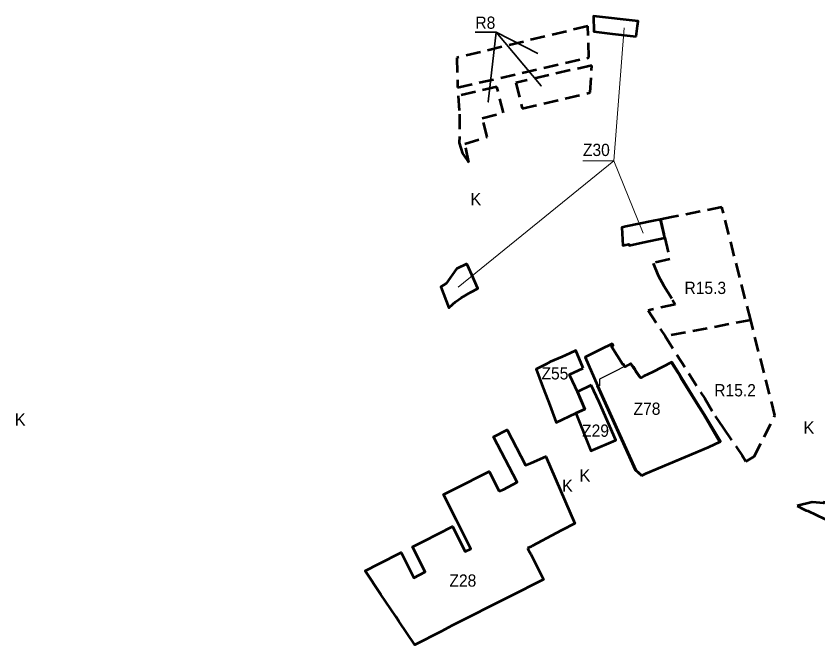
# Model space of a CAD drawing. Extents: x -650246 to -642674, y -1074280 to -1066767.
# Drawn here: x -649378 to -647810, y -1067997 to -1066767 of the extents above; entities that cross this region are included whole.
import ezdxf

# ---------------------------------------------------------------- set-up
doc = ezdxf.new("R2010")
doc.units = 0
doc.header["$LTSCALE"] = 9.6
doc.linetypes.add('MEDIUM_DASHED', pattern=[4.5, 3, -1.5])
for name, color, linetype, lineweight in [('42', 7, 'Continuous', 25), ('44', 7, 'Continuous', 53), ('45', 7, 'Continuous', 53), ('46', 7, 'Continuous', 13), ('48', 7, 'Continuous', 13), ('61', 7, 'MEDIUM_DASHED', 53), ('62', 7, 'Continuous', 35)]:
    doc.layers.add(name, color=color, linetype=linetype, lineweight=lineweight)

msp = doc.modelspace()

# ---------------------------------------------------------------- linework, layer by layer
at = {"layer": '42'}
msp.add_lwpolyline([(-648155.972, -1067665.834), (-648151.925, -1067664.05), (-648148.202, -1067661.704), (-648025.952, -1067610.534), (-648002.622, -1067599.544), (-648033.762, -1067547.004), (-648047.032, -1067525.554), (-648078.312, -1067475.004), (-648083.302, -1067466.944), (-648097.272, -1067444.464), (-648135.552, -1067463.604), (-648152.452, -1067472.064), (-648157.842, -1067474.754), (-648166.232, -1067462.554), (-648168.962, -1067458.584), (-648172.372, -1067453.634), (-648177.932, -1067447.294), (-648189.432, -1067453.204), (-648205.382, -1067461.394), (-648236.672, -1067477.464), (-648236.862, -1067490.304), (-648242.502, -1067490.304), (-648168.165, -1067655.257)], close=True, dxfattribs=at)
at = {"layer": '44'}
for points in [[(-647695.797, -1067753.719), (-647697.85, -1067749.46), (-647699.89, -1067745.24), (-647702.21, -1067740.43), (-647708.71, -1067723.99), (-647720.45, -1067726.49), (-647732.71, -1067727.02), (-647745.41, -1067726.6), (-647768.53, -1067722.82), (-647783.13, -1067719.68), (-647798.17, -1067717.58), (-647798.5, -1067719.67), (-647821.02, -1067717.33), (-647850.45, -1067724.77)], [(-647850.45, -1067724.77), (-647838.18, -1067731.62), (-647832.56, -1067734.22), (-647829.49, -1067734.58), (-647796.87, -1067750.25), (-647774.54, -1067758.68), (-647753.53, -1067765.58), (-647718.54, -1067770.6), (-647712.01, -1067769.63), (-647712.26, -1067767.28)]]:
    msp.add_lwpolyline(points, dxfattribs=at)
at = {"layer": '45'}
for points in [[(-648165.33, -1066807.74), (-648162.8, -1066786.8), (-648161.58, -1066777.41), (-648248.77, -1066767.43), (-648247.78, -1066797.53), (-648211.58, -1066802.18)], [(-648165.33, -1066807.74), (-648162.8, -1066786.8), (-648161.58, -1066777.41), (-648248.77, -1066767.43), (-648247.78, -1066797.53), (-648211.58, -1066802.18)], [(-648185.185, -1067178.687), (-648193.02, -1067180.66), (-648191.44, -1067215.62), (-648179.42, -1067213.37), (-648179, -1067215.71), (-648152.5, -1067210.23), (-648109.1, -1067201.21), (-648117.51, -1067165.42), (-648131.01, -1067167.84)], [(-648185.185, -1067178.687), (-648193.02, -1067180.66), (-648191.44, -1067215.62), (-648179.42, -1067213.37), (-648179, -1067215.71), (-648152.5, -1067210.23), (-648109.1, -1067201.21), (-648117.51, -1067165.42), (-648131.01, -1067167.84)], [(-648496.55, -1067251.53), (-648516.47, -1067261.54), (-648536.84, -1067290.29), (-648547.17, -1067296.68), (-648531.51, -1067337.57), (-648523.55, -1067330.33), (-648518.55, -1067326.3), (-648507.25, -1067318.35), (-648488.66, -1067307.11), (-648474.69, -1067299.66), (-648486.79, -1067273.26), (-648492.62, -1067260.53)], [(-648496.55, -1067251.53), (-648516.47, -1067261.54), (-648536.84, -1067290.29), (-648547.17, -1067296.68), (-648531.51, -1067337.57), (-648523.55, -1067330.33), (-648518.55, -1067326.3), (-648507.25, -1067318.35), (-648488.66, -1067307.11), (-648474.69, -1067299.66), (-648486.79, -1067273.26), (-648492.62, -1067260.53)], [(-648153.98, -1067665.43), (-648149.933, -1067663.646), (-648146.21, -1067661.3), (-648023.96, -1067610.13), (-648000.63, -1067599.14), (-648031.77, -1067546.6), (-648045.04, -1067525.15), (-648076.32, -1067474.6), (-648081.31, -1067466.54), (-648095.28, -1067444.06), (-648133.56, -1067463.2), (-648150.46, -1067471.66), (-648155.85, -1067474.35), (-648164.24, -1067462.15), (-648166.97, -1067458.18), (-648170.38, -1067453.23), (-648175.94, -1067446.89), (-648187.44, -1067452.8), (-648190.23, -1067447.83), (-648191.46, -1067448.59), (-648213.34, -1067413.46), (-648210.48, -1067411.68), (-648212.32, -1067408.39), (-648234.808, -1067419.29), (-648265.197, -1067434.03), (-648240.51, -1067489.9), (-648166.173, -1067654.853)], [(-648153.98, -1067665.43), (-648149.933, -1067663.646), (-648146.21, -1067661.3), (-648023.96, -1067610.13), (-648000.63, -1067599.14), (-648031.77, -1067546.6), (-648045.04, -1067525.15), (-648076.32, -1067474.6), (-648081.31, -1067466.54), (-648095.28, -1067444.06), (-648133.56, -1067463.2), (-648150.46, -1067471.66), (-648155.85, -1067474.35), (-648164.24, -1067462.15), (-648166.97, -1067458.18), (-648170.38, -1067453.23), (-648175.94, -1067446.89), (-648187.44, -1067452.8), (-648190.23, -1067447.83), (-648191.46, -1067448.59), (-648213.34, -1067413.46), (-648210.48, -1067411.68), (-648212.32, -1067408.39), (-648234.808, -1067419.29), (-648265.197, -1067434.03), (-648240.51, -1067489.9), (-648166.173, -1067654.853)], [(-648253.1, -1067489.23), (-648279.86, -1067502.11), (-648265.757, -1067535.555), (-648282.863, -1067543.596), (-648254.04, -1067616.96), (-648204.88, -1067596.54), (-648237.81, -1067522.42)], [(-648253.1, -1067489.23), (-648279.86, -1067502.11), (-648265.757, -1067535.555), (-648282.863, -1067543.596), (-648254.04, -1067616.96), (-648204.88, -1067596.54), (-648237.81, -1067522.42)]]:
    msp.add_lwpolyline(points, close=True, dxfattribs=at)
for points in [[(-648268.67, -1067455.43), (-648283.21, -1067420.88), (-648295.66, -1067426.76), (-648309.57, -1067433.34), (-648333.48, -1067443.28), (-648341.15, -1067448.14)], [(-648268.67, -1067455.43), (-648283.21, -1067420.88), (-648295.66, -1067426.76), (-648309.57, -1067433.34), (-648333.48, -1067443.28), (-648341.15, -1067448.14)], [(-648341.15, -1067448.14), (-648361, -1067457.36), (-648347.51, -1067492.87)], [(-648341.15, -1067448.14), (-648361, -1067457.36), (-648347.51, -1067492.87)], [(-648279.86, -1067502.11), (-648294.04, -1067471.35), (-648295.409, -1067468.129), (-648268.67, -1067455.43)], [(-648279.86, -1067502.11), (-648294.04, -1067471.35), (-648295.409, -1067468.129), (-648268.67, -1067455.43)], [(-648347.51, -1067492.87), (-648346.27, -1067496.14), (-648334.09, -1067528.2), (-648321.36, -1067561.69), (-648282.863, -1067543.596)], [(-648347.51, -1067492.87), (-648346.27, -1067496.14), (-648334.09, -1067528.2), (-648321.36, -1067561.69), (-648282.863, -1067543.596)], [(-648282.863, -1067543.596), (-648265.757, -1067535.555), (-648279.86, -1067502.11)], [(-648282.863, -1067543.596), (-648265.757, -1067535.555), (-648279.86, -1067502.11)], [(-648433.183, -1067696.369), (-648424.69, -1067692.54), (-648397.98, -1067678.79), (-648443.83, -1067589.92), (-648417.12, -1067576.17), (-648381.535, -1067645.274), (-648369.949, -1067640.851), (-648342.023, -1067628.096), (-648285.254, -1067759.008), (-648310.511, -1067772.476), (-648321.623, -1067778.399), (-648367.811, -1067802.994), (-648370.113, -1067804.22), (-648377.422, -1067807.337)], [(-648377.422, -1067807.337), (-648374.84, -1067812.43), (-648371.27, -1067819.47), (-648346.57, -1067868.56), (-648413.41, -1067902.53), (-648524.72, -1067958.93), (-648546.76, -1067970.44), (-648597.93, -1067996.72), (-648629.22, -1067950.214), (-648635.249, -1067941.252), (-648664.41, -1067897.91), (-648695.27, -1067852.04), (-648668.085, -1067838.186), (-648624.76, -1067816.11), (-648600.14, -1067865.29), (-648577.78, -1067854.07), (-648602.3, -1067804.83), (-648580.14, -1067793.61), (-648524.44, -1067765.11), (-648499.7, -1067814.37), (-648488.49, -1067808.76), (-648513.23, -1067759.38), (-648516.73, -1067752.57), (-648541.86, -1067702.86), (-648519.63, -1067691.58), (-648452.72, -1067657.62), (-648433.183, -1067696.369)]]:
    msp.add_lwpolyline(points, dxfattribs=at)
at = {"layer": '46'}
msp.add_lwpolyline([(-648269.459, -1067050.713), (-648208.812, -1067050.713), (-648188.893, -1066790.602), (-648208.812, -1067050.713), (-648151.62, -1067191.569), (-648208.812, -1067050.713), (-648513.485, -1067297.251)], dxfattribs=at)
msp.add_lwpolyline([(-648269.459, -1067050.713), (-648208.812, -1067050.713), (-648188.893, -1066790.602), (-648208.812, -1067050.713), (-648151.62, -1067191.569), (-648208.812, -1067050.713), (-648513.485, -1067297.251)], dxfattribs=at)
at = {"layer": '61'}
for points in [[(-648259.725, -1066787.254), (-648516.098, -1066849.061), (-648514.246, -1066907.231), (-648257.498, -1066848.545)], [(-648251.815, -1066863.877), (-648400.574, -1066897.877), (-648387.967, -1066948.136), (-648254.98, -1066916.96)], [(-648437.487, -1066905.774), (-648513.271, -1066923.097), (-648510.55, -1066959.48), (-648511.02, -1067015.58), (-648504.44, -1067035.85), (-648492.67, -1067053.5), (-648500.15, -1067017.22), (-648456.62, -1067003.59), (-648466.26, -1066967), (-648424.66, -1066956.87)], [(-647941.289, -1067362.104), (-648108.77, -1067393.23), (-648031.228, -1067515.162), (-648010.57, -1067549.31), (-647994.8, -1067572.37), (-647969.29, -1067609.79), (-647958.01, -1067626.32), (-647950.676, -1067638.328), (-647934.729, -1067628.389), (-647893.809, -1067548.531)]]:
    msp.add_lwpolyline(points, close=True, dxfattribs=at)
for points in [[(-647941.289, -1067362.104), (-647997.58, -1067141.08), (-648095.81, -1067160.82), (-648117.51, -1067165.42), (-648109.1, -1067201.21), (-648099.39, -1067242.54)], [(-648099.39, -1067242.54), (-648132.22, -1067250.27), (-648121.94, -1067274.29), (-648110.97, -1067294.96), (-648094.1, -1067322.05), (-648088.84, -1067331.19), (-648141.82, -1067342.88), (-648108.77, -1067393.23)]]:
    msp.add_lwpolyline(points, dxfattribs=at)
at = {"layer": '62'}
msp.add_lwpolyline([(-648480.094, -1066799.151), (-648438.938, -1066799.151), (-648454.468, -1066935.138), (-648438.938, -1066799.151), (-648351.131, -1066904.144), (-648438.938, -1066799.151), (-648357.401, -1066840.335)], dxfattribs=at)
at = {"layer": '62', "lineweight": 13}
msp.add_lwpolyline([(-648480.094, -1066799.151), (-648438.938, -1066799.151), (-648454.468, -1066935.138), (-648438.938, -1066799.151), (-648351.131, -1066904.144), (-648438.938, -1066799.151), (-648357.401, -1066840.335)], dxfattribs=at)

# ---------------------------------------------------------------- texts
at = {"layer": '46', "width": 0.95}
for s, p in [('Z30', (-648269.261, -1067041.062)), ('Z30', (-648269.261, -1067041.062)), ('Z55', (-648350.312, -1067477.755)), ('Z55', (-648350.312, -1067477.755)), ('Z78', (-648170.304, -1067546.968)), ('Z29', (-648270.915, -1067589.836)), ('Z29', (-648270.915, -1067589.836)), ('Z28', (-648530.318, -1067882.806)), ('Z28', (-648530.318, -1067882.806))]:
    msp.add_text(s, height=24, dxfattribs=at).set_placement(p)
at = {"layer": '48'}
for p in [(-648489.516, -1067137.308), (-648489.516, -1067137.308), (-649380.314, -1067568.167), (-649380.314, -1067568.167), (-647838.213, -1067583.936), (-648276.169, -1067677.278), (-648310.251, -1067697.408)]:
    msp.add_text('K', height=24, dxfattribs=at).set_placement(p)
at = {"layer": '62', "width": 0.95}
for s, p in [('R8', (-648479.548, -1066792.4)), ('R8', (-648479.548, -1066792.4)), ('R15.3', (-648070.747, -1067310.744)), ('R15.2', (-648012.511, -1067510.868))]:
    msp.add_text(s, height=24, dxfattribs=at).set_placement(p)

doc.saveas('drawing.dxf')
